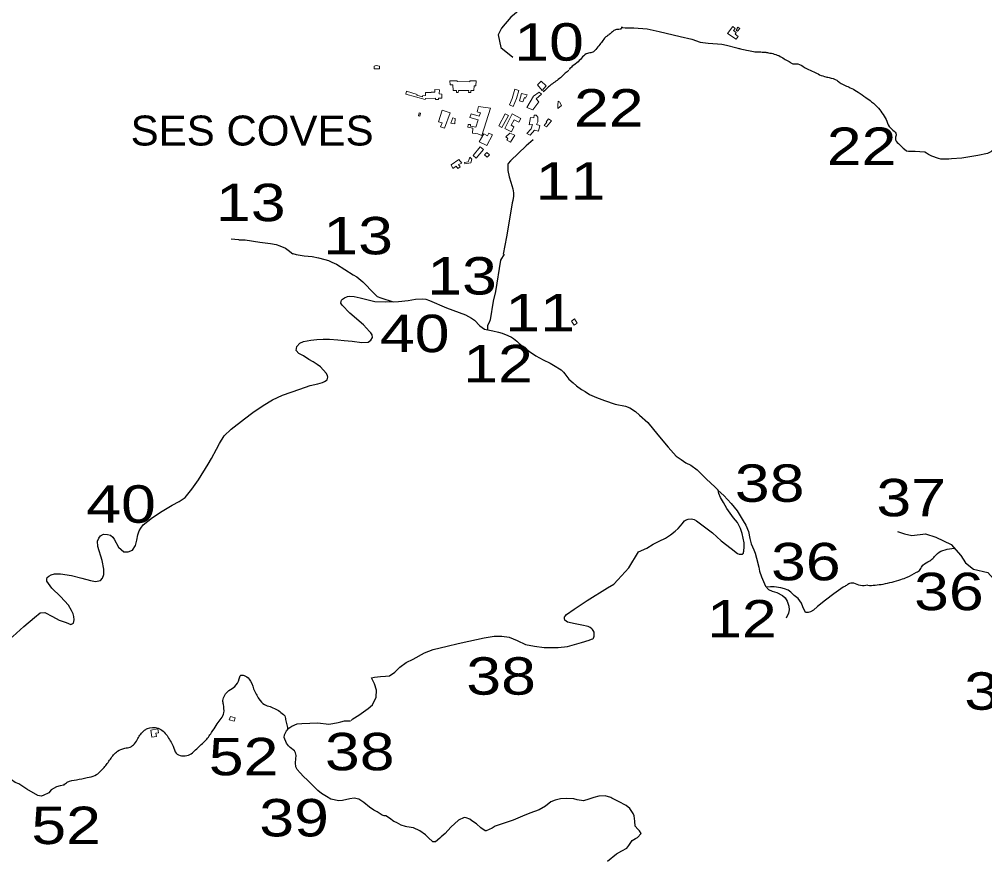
# Model space of a CAD drawing. Extents: x 476989 to 498418, y 4381813 to 4416555.
# Drawn here: x 484310 to 485600, y 4385643 to 4386760 of the extents above; entities that cross this region are included whole.
import ezdxf
from ezdxf.enums import TextEntityAlignment as Align

# ---------------------------------------------------------------- set-up
doc = ezdxf.new("R2010")
doc.units = 0
doc.header["$LTSCALE"] = 20
doc.linetypes.add('MEDIUM_DASHED', pattern=[4.5, 3, -1.5])
for name, color, linetype, lineweight in [('13', 7, 'Continuous', 13), ('47', 7, 'Continuous', 13), ('48', 7, 'MEDIUM_DASHED', 13), ('6', 7, 'Continuous', 25)]:
    doc.layers.add(name, color=color, linetype=linetype, lineweight=lineweight)
doc.layers.add('7', color=7, linetype='Continuous')

msp = doc.modelspace()

# ---------------------------------------------------------------- linework, layer by layer
at = {"layer": '47'}
for points in [[(485267.8, 4386733.43), (485256.48, 4386741.12), (485263.36, 4386750.59), (485266.67, 4386747.96), (485264.52, 4386745.08), (485268.18, 4386742.35), (485266.49, 4386740.36), (485270.62, 4386737.25)], [(485272.72, 4386747.91), (485269.84, 4386744.21), (485268.02, 4386745.4), (485269.25, 4386747.04), (485268.91, 4386747.33), (485270.37, 4386749.54)], [(484791.59, 4386697.69), (484791.41, 4386693.78), (484784.36, 4386694.03), (484784.57, 4386697.72), (484787.22, 4386698.3)], [(484912.38, 4386677.94), (484920.75, 4386677.78), (484920.46, 4386671.05), (484917.81, 4386671.05), (484917.39, 4386664.88), (484913.7, 4386664.88), (484913.51, 4386662.27), (484910.67, 4386662.23), (484910.82, 4386664.83), (484896.88, 4386664.88), (484896.69, 4386662.27), (484894.26, 4386662.29), (484894.38, 4386664.94), (484889.81, 4386664.95), (484889.46, 4386672.4), (484885.79, 4386672.68), (484885.72, 4386678.1), (484888.41, 4386678.06), (484895.26, 4386678.11), (484895.2, 4386676.96), (484912.45, 4386676.68)], [(485009.06, 4386664.93), (485002.56, 4386672.56), (485007.64, 4386677.52), (485014.09, 4386671.17)], [(484874.65, 4386654.69), (484870.48, 4386654.58), (484870.46, 4386653.02), (484866.58, 4386653.01), (484866.49, 4386654.59), (484853.21, 4386654.39), (484852.68, 4386652.83), (484826.61, 4386660.29), (484827.71, 4386664.28), (484842.06, 4386659.71), (484841.42, 4386658.6), (484849.07, 4386656.47), (484849.11, 4386658.07), (484852.95, 4386658.16), (484852.97, 4386662.54), (484860.65, 4386662.23), (484860.59, 4386662.87), (484865.39, 4386662.92), (484865.39, 4386666.55), (484871.56, 4386665.85), (484871.09, 4386660.58), (484874.62, 4386659.92)], [(484965.07, 4386645.88), (484968.64, 4386654.55), (484972.34, 4386666.93), (484977.49, 4386665.02), (484974.53, 4386654.43), (484969.91, 4386643.72)], [(484982.82, 4386649.95), (484978.55, 4386651.27), (484981.38, 4386660.9), (484988.94, 4386659.2), (484986.79, 4386654.97), (484985.12, 4386655.57)], [(484996.43, 4386639.1), (484988.3, 4386642.47), (484997.48, 4386657.34), (485004.88, 4386662.98), (485007.91, 4386660.32), (485001.03, 4386653.8), (485004.26, 4386650.11)], [(485030.11, 4386650.61), (485029.58, 4386644.86), (485029.99, 4386640.89), (485034.75, 4386645), (485031.79, 4386649.97)], [(484844.5, 4386635.18), (484846.55, 4386634.63), (484845.65, 4386630.54), (484843.47, 4386631)], [(484878.58, 4386614.5), (484885.94, 4386635.06), (484875.22, 4386638.61), (484870.18, 4386623.37), (484875.16, 4386621.77), (484873.26, 4386616.47)], [(484928.18, 4386605.08), (484939.97, 4386641.51), (484923.72, 4386643.6), (484923.72, 4386643.6), (484922.15, 4386636.75), (484926.42, 4386635.39), (484924.89, 4386630.56), (484914.1, 4386633.92), (484912.38, 4386628.99), (484923.2, 4386626.01), (484920.36, 4386615.87), (484913.03, 4386617.33), (484913.16, 4386619.43), (484910.06, 4386619.81), (484909.64, 4386615.9), (484916.17, 4386614.67), (484915.69, 4386607.82), (484923.12, 4386607.18)], [(484963.89, 4386631.61), (484955.07, 4386615.72), (484950.82, 4386617.68), (484959.38, 4386633.93)], [(484967.69, 4386609.95), (484958.91, 4386614.38), (484968.97, 4386633.65), (484980.35, 4386627.47), (484977.58, 4386622.58), (484971.41, 4386625.97), (484967.47, 4386618.74), (484971.14, 4386616.66)], [(484886.83, 4386621.49), (484889.37, 4386628.45), (484892.44, 4386627.58), (484892, 4386620.32)], [(484988.42, 4386607.8), (484994.31, 4386613.95), (484996.03, 4386619.44), (484991.42, 4386619.37), (484993.16, 4386629.13), (484997.81, 4386628.54), (484998.06, 4386632.15), (485000.73, 4386632.13), (485003.26, 4386629.33), (485003.18, 4386623.16), (485001.26, 4386619.51), (485005.92, 4386618.3), (485003.83, 4386610.74), (484998.71, 4386611.89), (484992.95, 4386605.26)], [(485011.45, 4386618.18), (485014.46, 4386616.41), (485021.54, 4386624.32), (485017.31, 4386627), (485014.34, 4386623.18), (485015.15, 4386622.6)], [(484930.93, 4386607.22), (484924.86, 4386596.58), (484934.84, 4386591.38), (484942.38, 4386605.69), (484937.68, 4386607.95), (484935.78, 4386604.53)], [(484966.64, 4386595.92), (484972.22, 4386605.45), (484965.86, 4386607.86), (484960.42, 4386603.19), (484963.09, 4386601.11), (484961.54, 4386598.91)], [(484930.53, 4386586.08), (484920.88, 4386574.84), (484916.58, 4386578.14), (484926.15, 4386589.6)], [(484931.93, 4386579.1), (484935.2, 4386575.97), (484938.33, 4386579.24), (484934.89, 4386582.26)], [(484897.59, 4386572.87), (484901.46, 4386567.77), (484897.1, 4386566.06), (484899.31, 4386562.89), (484896.16, 4386560.94), (484894.13, 4386564.12), (484889.43, 4386560.81), (484887.27, 4386565.75)], [(484911.46, 4386573.35), (484909.91, 4386569.85), (484905.06, 4386569.06), (484905.54, 4386567.13), (484913.36, 4386568.57), (484915.04, 4386573.28), (484912.15, 4386575.78)]]:
    msp.add_lwpolyline(points, close=True, dxfattribs=at)
at = {"layer": '48'}
for points in [[(485047.97, 4386357.07), (485051.39, 4386351.42), (485055.76, 4386354.03), (485052.03, 4386360.03)], [(484598.89, 4385827.25), (484597.24, 4385822.7), (484590.88, 4385824.37), (484592.65, 4385829.02)], [(484495.64, 4385812.34), (484486.27, 4385810.61), (484487.44, 4385801.36), (484493.55, 4385802.32), (484492.91, 4385806.73), (484496.44, 4385807.23)]]:
    msp.add_lwpolyline(points, close=True, dxfattribs=at)
at = {"layer": '6'}
msp.add_line((484669.78, 4386451.55), (484675.59, 4386447), dxfattribs=at)
for points in [[(485196.68, 4387001.41), (485174.53, 4386974.43), (485140.42, 4386936.16), (485108.67, 4386902.09), (485070.95, 4386860.47), (485042.96, 4386831.45), (485012.41, 4386802.17), (484984.19, 4386777.31), (484966.85, 4386762.96), (484954.68, 4386748.08), (484950.17, 4386739.57), (484953.68, 4386722.28), (484969.49, 4386709.51)], [(485115.8, 4386749.57), (485116.23, 4386749.1), (485119.88, 4386748.84), (485125.2, 4386748.79), (485131.48, 4386748.94), (485148.96, 4386747.36), (485165.08, 4386743.99), (485193.34, 4386737.28), (485208.6, 4386733.52), (485219.97, 4386729.79), (485230.45, 4386728.1), (485243, 4386727.43), (485248.7, 4386726.99), (485255.02, 4386725.5), (485268.69, 4386722.23)], [(484996.82, 4386599.17), (484987.66, 4386591.04), (484966.55, 4386571), (484963.37, 4386567.3), (484963.02, 4386566.37), (484962.82, 4386558.23), (484964.9, 4386549.85), (484966.92, 4386542.55), (484969.46, 4386533.86), (484970.42, 4386528.49), (484970.53, 4386524.01), (484969.46, 4386518.29), (484968.88, 4386515.18), (484965.99, 4386498.52), (484961.18, 4386469.77), (484956.92, 4386446.46)], [(485614.42, 4386588.88), (485608.24, 4386583.25), (485603.79, 4386581.02), (485590.67, 4386577.99), (485569.57, 4386574.82), (485555.53, 4386573.67), (485552.14, 4386573.42), (485549.36, 4386573.22), (485546.88, 4386573.26), (485541.5, 4386573.42), (485538.28, 4386574.27), (485529.3, 4386577.31), (485524.93, 4386579.57), (485522.13, 4386581.47), (485519.82, 4386582.6), (485513.12, 4386583.13), (485507.1, 4386583.36), (485502.68, 4386583.42), (485498.06, 4386583.56), (485495.44, 4386583.92), (485492.88, 4386586.05)], [(484593.43, 4386466.83), (484593.45, 4386466.82), (484603.22, 4386466), (484604.19, 4386465.78), (484612, 4386465.4), (484631.54, 4386462.29), (484646.09, 4386460.77), (484653.53, 4386459.28), (484658.44, 4386457.47), (484658.41, 4386457.42), (484665.79, 4386454.57), (484669.78, 4386451.55)], [(484675.58, 4386447.22), (484680.33, 4386445.85), (484691.09, 4386444.37), (484701.51, 4386443.23), (484710.08, 4386441.49), (484718.53, 4386439.37), (484723.57, 4386437.83), (484728.11, 4386435.66), (484734.03, 4386433), (484745.31, 4386426.03), (484756.55, 4386418.6), (484761.33, 4386415.93), (484769.5, 4386409.28), (484784.5, 4386393.85), (484788.56, 4386389.73), (484793.23, 4386388.09), (484809.87, 4386382.9)], [(484958.3, 4386446.26), (484953.04, 4386438.59), (484946.62, 4386396.38), (484943.54, 4386383.67), (484939.22, 4386358.89), (484937.9, 4386355.26), (484935.85, 4386351.35), (484935.78, 4386345.49)], [(484685.19, 4386265.93), (484699.05, 4386271.21), (484709.17, 4386273.3), (484715.34, 4386275.16), (484718.26, 4386276.38), (484721.48, 4386278.67), (484722.61, 4386282.28), (484722.26, 4386284.54), (484720.47, 4386287.55), (484712.75, 4386295.74), (484708.14, 4386299.06), (484702.94, 4386302.54), (484697.3, 4386305.69), (484689.87, 4386310.65), (484683.82, 4386313.61), (484680.3, 4386317.64), (484681.25, 4386322.94), (484685, 4386327.62), (484690.15, 4386329.65), (484694.88, 4386330.51), (484699.71, 4386331.42), (484707.82, 4386332.39), (484716.34, 4386332.7), (484724.64, 4386332.71), (484735.89, 4386332.21), (484744.5, 4386331.21), (484755.17, 4386329.99), (484767.77, 4386328.32), (484776.22, 4386328.88), (484780.04, 4386331.64), (484782.17, 4386335), (484781.89, 4386338.8), (484780.11, 4386341.21), (484778.3, 4386343.08), (484770.28, 4386352.19), (484752.12, 4386367.49), (484741.53, 4386378.26), (484740.11, 4386380.91), (484740.18, 4386383.41), (484740.83, 4386384.77), (484742.14, 4386386.31), (484744.9, 4386388.13), (484748.72, 4386389.71), (484752.02, 4386390.1), (484757.64, 4386389.92), (484765.75, 4386388.13), (484785.25, 4386383.31), (484799.6, 4386382.75), (484816.87, 4386383.07), (484829.76, 4386384.43), (484839.45, 4386386.17), (484849.35, 4386386.59), (484853.26, 4386386.23), (484858.54, 4386384.32), (484881.13, 4386374.95), (484906.55, 4386365.25), (484914.67, 4386360.86), (484918.39, 4386358.2), (484925.44, 4386350.65), (484931.98, 4386346.41), (484938.51, 4386345.07), (484942.87, 4386343.84)], [(484942.87, 4386343.84), (484950.32, 4386342.24), (484955.52, 4386340.89), (484963.01, 4386337.82), (484967.78, 4386335.39), (484970.48, 4386333.62), (484974.91, 4386330.09), (484978.3, 4386327.13), (484983.78, 4386322.85), (484991.83, 4386316.23), (485000.22, 4386310.65), (485010.22, 4386305.49), (485019.61, 4386300.9), (485023.89, 4386297.97), (485034.3, 4386291.84), (485037.17, 4386288.93), (485039.13, 4386286.4), (485044.46, 4386279.63), (485050.26, 4386274.45), (485054.6, 4386270.52), (485061.48, 4386265.69), (485066.31, 4386262.9), (485072.11, 4386258.98), (485081.56, 4386254.75), (485092.29, 4386251), (485106.38, 4386246.15), (485120.38, 4386243.3), (485125.75, 4386241.04), (485133.62, 4386236.48), (485138.8, 4386231.28), (485150.15, 4386221.79), (485163.42, 4386205.22), (485177.27, 4386188.83), (485187.8, 4386176.49), (485194.39, 4386172.03), (485200.95, 4386167.78), (485207.56, 4386164.49), (485215.71, 4386158.18), (485220.87, 4386153.67), (485228.5, 4386145.73), (485239.66, 4386135.6), (485243.92, 4386131.21)], [(484379.37, 4385951.8), (484382.66, 4385953.41), (484383.69, 4385958.07), (484383.38, 4385962.64), (484382.38, 4385966.13), (484380.36, 4385970.61), (484376.08, 4385977.48), (484365.25, 4385989.07), (484353.82, 4386000.13), (484347.19, 4386009.82), (484347.05, 4386012.71), (484347.75, 4386014.63), (484350.02, 4386016.52), (484352.81, 4386018.1), (484357.54, 4386019.26), (484364.31, 4386019.32), (484365.47, 4386019.23), (484380.1, 4386017.06), (484394.06, 4386013.66), (484405.63, 4386010.39), (484412.36, 4386009.4), (484418.84, 4386010.62), (484421.41, 4386013.67), (484423.43, 4386018.43), (484423.38, 4386025.55), (484421.08, 4386037.22), (484415.43, 4386056.06), (484414.66, 4386063.2), (484416.5, 4386067.21), (484419.08, 4386070.17), (484423.1, 4386072.23), (484428.44, 4386071.87), (484432.24, 4386070.97), (484435.37, 4386068.48), (484437.13, 4386065.76), (484442.92, 4386055.26), (484450.13, 4386048.79), (484456.05, 4386048.77), (484461.7, 4386051.08), (484465.57, 4386057.36), (484467.35, 4386064.5), (484468.65, 4386071.5), (484470.33, 4386076.74), (484472.67, 4386080.51), (484476.1, 4386084.8), (484488.44, 4386094.73), (484501.37, 4386103.34), (484514.77, 4386111.11), (484523.77, 4386116.07), (484532.01, 4386121.17), (484540.68, 4386132.52), (484549.93, 4386145.08), (484562.6, 4386165.73), (484567.13, 4386173.42), (484573.89, 4386186.16), (484577.92, 4386193.43), (484584.11, 4386203.94), (484593.25, 4386212.62), (484611.2, 4386226.27), (484622.57, 4386235.08), (484636.27, 4386244.07), (484648.45, 4386251.66), (484662.04, 4386258.08), (484685.19, 4386265.93)], [(485137.42, 4386048.97), (485148.63, 4386053.82), (485157.15, 4386059.18), (485164.93, 4386062.86), (485173.69, 4386066.86), (485180.28, 4386071.55), (485186.41, 4386076.63), (485190.45, 4386080.03), (485193.63, 4386083.43), (485195.76, 4386086.35), (485199.08, 4386090.25), (485200.34, 4386091.24), (485203.86, 4386092.43), (485208.21, 4386092.7), (485211.9, 4386092.03), (485215.19, 4386090.42), (485225.5, 4386082.35), (485236.31, 4386074.25), (485247.96, 4386063.67), (485261.46, 4386053.34), (485269.97, 4386046.64), (485272.18, 4386045.77), (485274.75, 4386045.53), (485276.27, 4386045.91), (485277.39, 4386046.58), (485277.29, 4386046.46), (485277.27, 4386046.28), (485277.91, 4386048.23), (485278.42, 4386049.78), (485278.61, 4386055.69), (485278.62, 4386060.86), (485277.55, 4386067.01), (485276.23, 4386073.52), (485274, 4386079.95), (485269.68, 4386088.07), (485264.45, 4386094.26), (485259.77, 4386100.29), (485255.39, 4386106.74), (485251.08, 4386114.81), (485247.23, 4386121.17), (485244.96, 4386126.54), (485243.92, 4386131.21)], [(485244.01, 4386130.88), (485251.73, 4386124.05), (485261.17, 4386113.52), (485269.16, 4386103.38), (485277.47, 4386090.36), (485281.02, 4386084.45), (485284.58, 4386076.08), (485286.34, 4386066.85), (485288.02, 4386059.68), (485291.51, 4386051.58), (485293.26, 4386046.93), (485295.26, 4386040.29), (485298.32, 4386028.5), (485299.16, 4386022.88), (485301.83, 4386015.45), (485307.25, 4386003.05), (485311.27, 4385998.43), (485316.17, 4385996.13), (485322.45, 4385994.43), (485329.69, 4385990.5), (485333.27, 4385987.49), (485336.16, 4385982.91), (485338.39, 4385976.12), (485338.64, 4385971.4), (485337.85, 4385966.8), (485334.87, 4385960.03)], [(485483.32, 4386075.85), (485492.95, 4386072.64), (485502.59, 4386070.51), (485520.79, 4386072.64), (485534.7, 4386068.37), (485555.04, 4386058.75), (485567.89, 4386043.78), (485574.31, 4386034.16), (485585.02, 4386025.61), (485604.29, 4386021.34), (485611.78, 4386012.79), (485612.86, 4385999.96), (485619.28, 4385980.72)], [(484753.57, 4385823.35), (484756.07, 4385825.8), (484763.83, 4385830.53), (484776.58, 4385839.37), (484782.34, 4385844.43), (484787.2, 4385854.84), (484787.51, 4385863.86), (484784.87, 4385872.53), (484782.19, 4385877.63), (484780.99, 4385880.64), (484784.76, 4385881.31), (484793.02, 4385882.42), (484799.69, 4385882.89), (484804.87, 4385883.25), (484812.21, 4385887.91), (484818.61, 4385894.93), (484827.29, 4385900.91), (484836.49, 4385905.57), (484851.49, 4385914.04), (484863.4, 4385918.36), (484882.15, 4385922.96), (484896.7, 4385926.47), (484910.78, 4385929.65), (484931.26, 4385933.88), (484944.85, 4385936.14), (484954.98, 4385936.35), (484964.69, 4385934.66), (484975.5, 4385930.27), (484986.54, 4385925.21), (484998.58, 4385922.91), (485011.63, 4385921.23), (485030.11, 4385921.12), (485042.66, 4385922.44), (485061.41, 4385927.72), (485071.46, 4385930.94), (485074.81, 4385932.11), (485076.32, 4385932.73), (485076.79, 4385932.96), (485077.28, 4385933.45), (485078.11, 4385936.24), (485078.35, 4385938.73), (485078.24, 4385941.42), (485077.1, 4385943.96), (485076.09, 4385945.28), (485075.2, 4385946.11), (485073.05, 4385947.62), (485070.18, 4385948.95), (485061.85, 4385950.92), (485052.97, 4385952.73), (485042.57, 4385954.94), (485040.72, 4385956.12), (485039.31, 4385957.48), (485038.69, 4385959.31), (485038.59, 4385960.67), (485038.85, 4385961.89), (485039.56, 4385963.1), (485041.35, 4385965.05), (485051.42, 4385972.39), (485069, 4385983.72), (485096.24, 4386000.56), (485104.76, 4386005.49), (485110.15, 4386011.63), (485124.59, 4386027.56), (485137.59, 4386048.93)], [(485360.44, 4385967.89), (485357.02, 4385975.21), (485355.18, 4385980.08), (485350.75, 4385986.5), (485345.66, 4385990.53), (485341.11, 4385995.13), (485337.24, 4385997.82), (485332.38, 4385999.2), (485327.57, 4386000.86), (485318.71, 4386002.15), (485313.97, 4386002.06), (485308.63, 4386001.53)], [(485410.77, 4386001.69), (485398.53, 4385992.68), (485387.19, 4385984.33), (485376.75, 4385975.81), (485371.33, 4385971.08), (485367.37, 4385968.65), (485364.11, 4385967.7), (485360.44, 4385967.89)], [(484330.76, 4385961.22), (484338.28, 4385967.32), (484344.45, 4385967.94), (484354.95, 4385962.38), (484363.6, 4385957.45), (484372.86, 4385954.36), (484379.37, 4385951.8)], [(484103.92, 4385718.57), (484111.72, 4385728.95), (484132.39, 4385753.72), (484150.74, 4385776.42), (484168.25, 4385798.21), (484178.85, 4385811.99), (484192.12, 4385829), (484210.84, 4385851.58), (484229.9, 4385876.92), (484247.2, 4385904.12), (484254.19, 4385912.82), (484258.83, 4385917.22), (484264.2, 4385920.12), (484276.08, 4385925.76), (484289.25, 4385930.22), (484301.63, 4385935.61), (484316.4, 4385948.98), (484330.76, 4385961.22)], [(484800.3, 4385696.28), (484798.02, 4385696.13), (484794.95, 4385697.11), (484788.65, 4385701.33), (484784.14, 4385703.65), (484778.1, 4385707.87), (484770.66, 4385714.12), (484763.99, 4385718.53), (484757.75, 4385719.78), (484751.75, 4385719.07), (484741.98, 4385716.54), (484737.22, 4385716.32), (484726.74, 4385718.66), (484720.63, 4385722.11), (484713.97, 4385725.94), (484709.05, 4385730.17), (484700.76, 4385738.7), (484695.42, 4385743.75), (484690.09, 4385748.53), (484685.65, 4385753.67), (484681.68, 4385758.04), (484679.8, 4385761.6), (484679.52, 4385766.78), (484679.87, 4385772.29), (484680.17, 4385776.84), (484679.5, 4385780.26), (484677.94, 4385783.18), (484672.46, 4385787.45), (484670.1, 4385789.86), (484667.17, 4385793.46), (484664.19, 4385800.81), (484664.55, 4385804.26), (484667.17, 4385809.62), (484670.46, 4385813.3), (484674.66, 4385816.15), (484681.59, 4385818.87), (484687.68, 4385819.41), (484687.98, 4385819.58), (484709.29, 4385820.21), (484723.73, 4385818.84), (484729.17, 4385819.65), (484736.43, 4385820.77), (484740.02, 4385821.59), (484744.86, 4385823.22), (484752.62, 4385823.08)], [(484369.87, 4385737.2), (484364.99, 4385736.16), (484360, 4385734.88), (484353.19, 4385731.05), (484349.68, 4385726.82), (484342.51, 4385723.3), (484339.54, 4385722.65), (484335.38, 4385723.47), (484320.6, 4385731.82), (484309.66, 4385739), (484305.07, 4385740.5), (484294.96, 4385748), (484290.13, 4385755.39), (484288.41, 4385763.09), (484288.39, 4385763.58)], [(485096.05, 4385635.71), (485108.29, 4385645.35), (485115.31, 4385649.61), (485121.88, 4385653.16), (485124.79, 4385656.54), (485129.25, 4385663.08), (485133.36, 4385665.71), (485136.36, 4385667.21), (485141.15, 4385672.45), (485138.98, 4385676.34), (485136.6, 4385678.19), (485132.96, 4385682.34), (485132.73, 4385689.27), (485131.61, 4385696.11), (485130.61, 4385699.3), (485126.06, 4385705.79), (485120.96, 4385709.83), (485110.68, 4385715.36), (485102.13, 4385719.83), (485100.43, 4385720.52), (485092.99, 4385723.04), (485084.43, 4385722.63), (485077.87, 4385720.89), (485071.23, 4385718.34), (485064, 4385716.41), (485055.4, 4385717.72), (485051.11, 4385718.81), (485041.54, 4385719.28), (485033.36, 4385718.73), (485026.4, 4385717.08), (485020.65, 4385715.06), (485013.23, 4385708.97), (485004.94, 4385704.27), (484992.48, 4385699.86), (484982.68, 4385695.78), (484970.33, 4385690.54), (484945.93, 4385682.49), (484941.89, 4385679.67), (484934.03, 4385676.17), (484932.74, 4385676.12), (484927.13, 4385680.21), (484921, 4385685.64), (484914.97, 4385689.73), (484912.08, 4385691.8), (484907.48, 4385693.68), (484904.82, 4385693.81), (484897.05, 4385690.33), (484887.01, 4385681), (484879.15, 4385672.55), (484873.88, 4385668.07), (484872, 4385666.15), (484866.47, 4385661.44), (484862.95, 4385661.58), (484856.78, 4385667.28), (484853.08, 4385670.62), (484845.41, 4385676.06), (484837.17, 4385680.06), (484828.17, 4385681.33), (484826.1, 4385681.74), (484820.37, 4385683.92), (484814.41, 4385687.36), (484810.87, 4385688.46), (484804.79, 4385692.89), (484800.15, 4385696.36)]]:
    msp.add_lwpolyline(points, dxfattribs=at)
for points in [[(485115.36, 4386750.06), (485114.19, 4386747.52), (485113.18, 4386746.88), (485109.53, 4386746.71), (485104.69, 4386745.06), (485100.59, 4386741.44), (485096.18, 4386738.34), (485093.43, 4386736.08), (485088.97, 4386730.52), (485084.71, 4386724.86), (485079.08, 4386718.3), (485075.29, 4386715.77), (485069.5, 4386714.61), (485062.95, 4386709.95), (485056.92, 4386703.52), (485049.07, 4386697.32), (485044.98, 4386693.19)], [(485269.25, 4386721.86), (485273.58, 4386720.69), (485281.99, 4386718.99), (485291.13, 4386717.08), (485298.97, 4386716.54), (485306.16, 4386716.18), (485311.27, 4386715.46), (485318.78, 4386713.76), (485326.94, 4386710.61), (485333.63, 4386706.4), (485340.32, 4386702.69), (485343.71, 4386700.79), (485350.33, 4386700.57), (485359.32, 4386695.9), (485369.58, 4386690.94), (485377.37, 4386687.13), (485386.17, 4386683.79), (485392.17, 4386682.32), (485402.4, 4386678.62), (485406.74, 4386675.4), (485420.48, 4386668.69), (485428.53, 4386664.29), (485438.68, 4386657.3), (485441.05, 4386655.72), (485448.83, 4386650.03), (485458.08, 4386641.35), (485464.26, 4386632.88), (485469.2, 4386623.92), (485470.98, 4386618.97), (485477.37, 4386612.21), (485481.67, 4386606.48), (485480.65, 4386601.56), (485480.95, 4386599.19), (485486.47, 4386592.56), (485492.66, 4386586.48)], [(485044.48, 4386692.16), (485035.19, 4386683.87), (485033.34, 4386682.1), (485020.94, 4386672.97), (485016.38, 4386668.89), (485010.36, 4386663.05)], [(485443.74, 4386004.16), (485443.83, 4386004.15), (485453.51, 4386004.46), (485464.41, 4386005.81), (485476.23, 4386008.42), (485488.14, 4386011.85), (485496.43, 4386014.96), (485508.98, 4386021.45), (485513.76, 4386025.14), (485517.53, 4386031.09), (485526.61, 4386036.58), (485536.73, 4386046.57), (485559.1, 4386053.59)], [(485443.74, 4386004.16), (485434.22, 4386003.76), (485425.36, 4386006.76), (485422.62, 4386007.16), (485419.49, 4386006.67), (485415.18, 4386003.87), (485410.89, 4386001.79)], [(484369.69, 4385737.23), (484374.57, 4385741.25), (484387.05, 4385744.42), (484401.1, 4385747.22), (484411.47, 4385750.14), (484418.64, 4385755.36), (484427.98, 4385766.15), (484436.47, 4385777.61), (484441.49, 4385782.4), (484451.37, 4385786.51), (484458.52, 4385788.13), (484464.47, 4385792.51), (484468.73, 4385799.27), (484477.71, 4385810.44), (484481.55, 4385812.74), (484495.71, 4385813.19), (484507.73, 4385803.27), (484511.98, 4385796.51), (484516.11, 4385789.27), (484519.94, 4385779.82), (484536.29, 4385777.31), (484548.82, 4385787.09), (484560.77, 4385798.6), (484569.09, 4385810.32), (484574.95, 4385818.97), (484583.57, 4385833.88), (484582.99, 4385844.94), (484582.37, 4385850.18), (484590.45, 4385863.44), (484598.39, 4385869.16), (484604.27, 4385879.03), (484606.52, 4385884.01), (484610.62, 4385883.7), (484617.41, 4385878.95), (484623.48, 4385865.81), (484630.54, 4385852.41), (484637.92, 4385844.92), (484645.47, 4385842.02), (484653.1, 4385838.51), (484656.48, 4385836.87), (484663.31, 4385831.44), (484664.35, 4385830.75), (484665.94, 4385824.73), (484667.79, 4385817.91), (484668.54, 4385814.07), (484669.03, 4385811.7)]]:
    msp.add_spline(points, degree=3, dxfattribs=at)

# ---------------------------------------------------------------- texts
at = {"layer": '13', "width": 1.25}
for s, p in [('10', (485018.06, 4386704.9)), ('22', (485097.88, 4386616.91)), ('22', (485435.5, 4386565.58)), ('11', (485046.7, 4386519.24)), ('13', (484619.71, 4386490.5)), ('13', (484763.07, 4386446.16)), ('13', (484901.82, 4386392.49)), ('11', (485006.11, 4386343.25)), ('40', (484838.61, 4386315.54)), ('12', (484949.89, 4386275.21)), ('38', (485312.74, 4386115.62)), ('37', (485501.81, 4386096.28)), ('40', (484446.34, 4386087.68)), ('36', (485361.09, 4386010.77)), ('36', (485552.18, 4385970.88)), ('12', (485275.65, 4385934.42)), ('38', (484954.01, 4385858.01)), ('37', (485619.21, 4385837.89)), ('38', (484765.19, 4385757.02)), ('52', (484610.04, 4385750.33)), ('39', (484677.48, 4385668.68)), ('52', (484373, 4385658.47))]:
    msp.add_text(s, height=50, dxfattribs=at).set_placement(p, align=Align.CENTER)
at = {"layer": '7', "width": 1.05}
msp.add_text('SES COVES', height=40, dxfattribs=at).set_placement((484621.43, 4386591.55), align=Align.CENTER)

doc.saveas('drawing.dxf')
